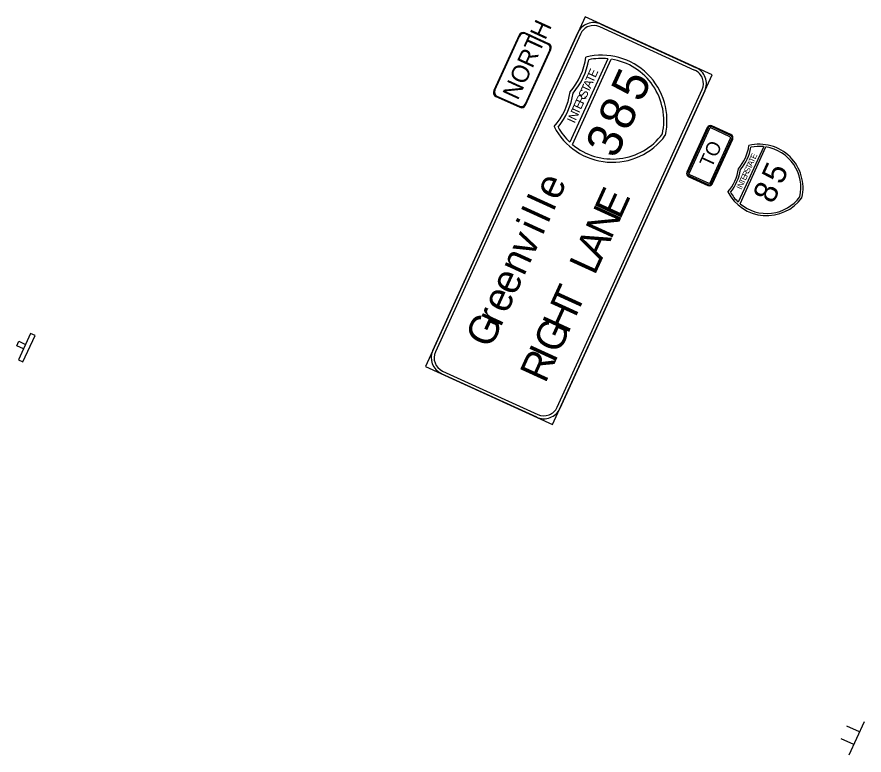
# Model space of a CAD drawing. Extents: x 1581789 to 1622364, y 1043167 to 1103486.
# Drawn here: x 1612864.4 to 1613107, y 1090205.7 to 1090417 of the extents above; entities that cross this region are included whole.
import ezdxf

# ---------------------------------------------------------------- set-up
doc = ezdxf.new("R2010")
doc.units = 0
doc.layers.add('RD_PD_ALT1_TX', color=7, linetype='Continuous')
doc.layers.add('RD_PD_PaveDit', color=7, linetype='Continuous')

msp = doc.modelspace()

# ---------------------------------------------------------------- linework, layer by layer
at = {"layer": 'RD_PD_ALT1_TX'}
for p, q in [((1613105.66, 1090212.31), (1613102.03, 1090213.96)), ((1613106.96, 1090215.15), (1613102.63, 1090205.66)), ((1613104, 1090208.65), (1613100.37, 1090210.31))]:
    msp.add_line(p, q, dxfattribs=at)
for points in [[(1612866.08, 1090318.27), (1612869.58, 1090325.83), (1612868.32, 1090326.42), (1612864.82, 1090318.85)], [(1612864.39, 1090322.88), (1612864.97, 1090324.14), (1612866.86, 1090323.27), (1612866.28, 1090322)]]:
    msp.add_lwpolyline(points, close=True, dxfattribs=at)
at = {"layer": 'RD_PD_PaveDit'}
for p, q in [((1613008.2, 1090411.84), (1613000.94, 1090395.92)), ((1613016.68, 1090409.34), (1613009.86, 1090412.46)), ((1613009.97, 1090412.16), (1613016.39, 1090409.23)), ((1613001.23, 1090396.03), (1613008.31, 1090411.55)), ((1613017.01, 1090407.58), (1613009.93, 1090392.06)), ((1613010.03, 1090391.77), (1613017.3, 1090407.69)), ((1613033.62, 1090405.05), (1613022.72, 1090381.16)), ((1613023.45, 1090380.51), (1613034.59, 1090404.92)), ((1613001.56, 1090394.26), (1613008.38, 1090391.15)), ((1613001.85, 1090394.37), (1613008.27, 1090391.44)), ((1613009.52, 1090390.63), (1613009.52, 1090390.63)), ((1613062.06, 1090385.33), (1613056.25, 1090372.6)), ((1613062.29, 1090385.23), (1613056.47, 1090372.49)), ((1613068.57, 1090382.73), (1613063.11, 1090385.22)), ((1613068.74, 1090383.11), (1613063.28, 1090385.6)), ((1613068.84, 1090383.33), (1613063.38, 1090385.83)), ((1613062.67, 1090385.05), (1613056.85, 1090372.32)), ((1613062.92, 1090369.55), (1613068.73, 1090382.29)), ((1613063.3, 1090369.38), (1613069.11, 1090382.11)), ((1613063.52, 1090369.28), (1613069.34, 1090382.01)), ((1613078.22, 1090379.88), (1613070.95, 1090363.96)), ((1613071.44, 1090363.53), (1613078.86, 1090379.8)), ((1613056.74, 1090371.27), (1613062.2, 1090368.78)), ((1613056.84, 1090371.5), (1613062.3, 1090369.01)), ((1613057.02, 1090371.88), (1613062.48, 1090369.39))]:
    msp.add_line(p, q, dxfattribs=at)
for points in [[(1613017.77, 1090300.34), (1613063.45, 1090400.41), (1613027.06, 1090417.02), (1612981.38, 1090316.95), (1613017.77, 1090300.34), (1613017.77, 1090300.34)], [(1613031.61, 1090414.94), (1613058.9, 1090402.49)], [(1612983.46, 1090321.5), (1613024.98, 1090412.47)], [(1613025.74, 1090412.13), (1612984.22, 1090321.15)], [(1613058.55, 1090401.73), (1613031.26, 1090414.19)], [(1613019.09, 1090305.24), (1613060.61, 1090396.21)], [(1613061.37, 1090395.86), (1613019.85, 1090304.89)], [(1613013.22, 1090302.42), (1612985.93, 1090314.87)], [(1612986.28, 1090315.63), (1613013.57, 1090303.18)]]:
    msp.add_lwpolyline(points, dxfattribs=at)
for centre, radius, start, end in [((1613029.53, 1090410.4), 5, 65.4667, 155.4669), ((1613029.53, 1090410.4), 4.17, 65.4667, 155.4669), ((1613009.34, 1090411.32), 1.25, 65.4679, 155.4679), ((1613009.45, 1090411.03), 1.25, 65.4679, 155.4679), ((1613015.87, 1090408.1), 1.25, 335.4679, 65.4679), ((1613016.16, 1090408.2), 1.25, 335.4679, 65.4679), ((1613008.73, 1090408), 18.75, 318.4756, 352.4578), ((1613008.74, 1090408.08), 19.69, 319.0876, 350.3287), ((1613031.79, 1090387.33), 18.75, 347.0038, 103.7978), ((1613031.79, 1090387.33), 17.81, 84.086, 101.7894), ((1613031.81, 1090387.33), 17.81, 347.6025, 80.9958), ((1613056.82, 1090397.94), 5, 335.4667, 65.4669), ((1613056.82, 1090397.94), 4.17, 335.4667, 65.4669), ((1613002.07, 1090395.4), 1.25, 155.4679, 245.4679), ((1613002.37, 1090395.51), 1.25, 155.4679, 245.4679), ((1613004.18, 1090398.03), 18.75, 318.4756, 352.4578), ((1613004.13, 1090397.98), 19.69, 320.6048, 351.8459), ((1613008.79, 1090392.58), 1.25, 245.4679, 335.4679), ((1613008.9, 1090392.28), 1.25, 245.4679, 335.4679), ((1613034.9, 1090394.16), 18.75, 207.1356, 323.9296), ((1613034.9, 1090394.16), 17.81, 209.1438, 226.8471), ((1613062.97, 1090384.92), 1, 65.4638, 155.4638), ((1613062.97, 1090384.92), 0.75, 65.4638, 155.4638), ((1613062.97, 1090384.92), 0.333, 65.4638, 155.4638), ((1613034.92, 1090394.14), 17.81, 229.9376, 323.3309), ((1613068.43, 1090382.42), 0.333, 335.4638, 65.4638), ((1613068.43, 1090382.42), 0.75, 335.4638, 65.4638), ((1613068.43, 1090382.42), 1, 335.4638, 65.4638), ((1613076.99, 1090368.07), 12.5, 347.0038, 103.7978), ((1613061.62, 1090381.85), 12.5, 318.4756, 352.4578), ((1613061.63, 1090381.9), 13.12, 319.0875, 350.3286), ((1613076.99, 1090368.07), 11.87, 84.086, 101.7894), ((1613077.01, 1090368.07), 11.87, 347.6025, 80.9958), ((1613058.59, 1090375.21), 12.5, 318.4756, 352.4578), ((1613058.56, 1090375.17), 13.12, 320.6047, 351.8458), ((1613057.16, 1090372.18), 1, 155.4638, 245.4638), ((1613057.16, 1090372.18), 0.75, 155.4638, 245.4638), ((1613057.16, 1090372.18), 0.333, 155.4638, 245.4638), ((1613062.61, 1090369.69), 1, 245.4638, 335.4638), ((1613062.61, 1090369.69), 0.75, 245.4638, 335.4638), ((1613062.61, 1090369.69), 0.333, 245.4638, 335.4638), ((1613079.07, 1090372.62), 12.5, 207.1356, 323.9296), ((1613079.07, 1090372.62), 11.87, 209.1438, 226.8471), ((1613079.08, 1090372.61), 11.87, 229.9376, 323.3309), ((1612988.01, 1090319.42), 5, 155.4669, 245.4665), ((1612988.01, 1090319.42), 4.17, 155.4669, 245.4665), ((1613015.3, 1090306.97), 4.17, 245.4665, 335.4667), ((1613015.3, 1090306.97), 5, 245.4665, 335.4667)]:
    msp.add_arc(centre, radius, start, end, dxfattribs=at)

# ---------------------------------------------------------------- texts
for s, height, rotation, p in [('NORTH', 5, 65.4776, (1613007.81, 1090392.97)), ('E', 2.5, 65.4667, (1613030.03, 1090399.46)), ('5', 10, 65.4667, (1613043.23, 1090392.24)), ('T', 2.5, 65.4667, (1613029.34, 1090397.94)), ('T', 2.5, 65.4667, (1613028.05, 1090395.12)), ('A', 2.5, 65.4667, (1613028.63, 1090396.39)), ('S', 2.5, 65.4667, (1613027.31, 1090393.49)), ('E', 2.5, 65.4667, (1613025.87, 1090390.35)), ('R', 2.5, 65.4667, (1613026.57, 1090391.87)), ('8', 10, 65.4667, (1613039.47, 1090384)), ('N', 2.5, 65.4667, (1613024.44, 1090387.2)), ('T', 2.5, 65.4667, (1613025.18, 1090388.82)), ('I', 2.5, 65.4667, (1613024.07, 1090386.4)), ('3', 10, 65.4667, (1613035.9, 1090376.18)), ('TO', 4, 65.4638, (1613063.32, 1090373.58)), ('E', 1.67, 65.4666, (1613075.83, 1090376.16)), ('A', 1.67, 65.4666, (1613074.89, 1090374.11)), ('T', 1.67, 65.4666, (1613075.36, 1090375.14)), ('S', 1.67, 65.4666, (1613074.01, 1090372.18)), ('T', 1.67, 65.4666, (1613074.51, 1090373.27)), ('5', 6.67, 65.4666, (1613083.43, 1090368.74)), ('e', 8.33, 65.4667, (1613019.4, 1090364.13)), ('T', 1.67, 65.4666, (1613072.59, 1090369.07)), ('E', 1.67, 65.4666, (1613073.05, 1090370.08)), ('R', 1.67, 65.4666, (1613073.51, 1090371.1)), ('E', 8.33, 65.4667, (1613037.12, 1090358.79)), ('I', 1.67, 65.4666, (1613071.85, 1090367.45)), ('N', 1.67, 65.4666, (1613072.09, 1090367.98)), ('8', 6.67, 65.4666, (1613080.92, 1090363.25)), ('l', 8.33, 65.4667, (1613018.05, 1090361.16)), ('l', 8.33, 65.4667, (1613016.47, 1090357.7)), ('N', 8.33, 65.4667, (1613034.5, 1090353.05)), ('i', 8.33, 65.4667, (1613014.89, 1090354.25)), ('v', 8.33, 65.4667, (1613012.06, 1090348.05)), ('A', 8.33, 65.4667, (1613031.75, 1090347.03)), ('n', 8.33, 65.4667, (1613009.57, 1090342.59)), ('L', 8.33, 65.4667, (1613029.83, 1090342.81)), ('e', 8.33, 65.4667, (1613006.98, 1090336.92)), ('e', 8.33, 65.4667, (1613004.63, 1090331.76)), ('T', 8.33, 65.4667, (1613024.64, 1090331.44)), ('H', 8.33, 65.4667, (1613022.16, 1090326.01)), ('r', 8.33, 65.4667, (1613002.92, 1090328.02)), ('G', 8.33, 65.4667, (1613000.1, 1090321.83)), ('G', 8.33, 65.4667, (1613019.54, 1090320.27)), ('I', 8.33, 65.4667, (1613018.32, 1090317.61)), ('R', 8.33, 65.4667, (1613015.7, 1090311.87))]:
    msp.add_text(s, height=height, rotation=rotation, dxfattribs=at).set_placement(p)

doc.saveas('drawing.dxf')
